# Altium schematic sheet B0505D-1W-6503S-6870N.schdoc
size 277 x 190 mm; Device: default297x210; Symbol: default297x210; Name: default297x210; Size: "A4"; Id: /; File: B0505D-1W-6503S-6870N; Sheet: /
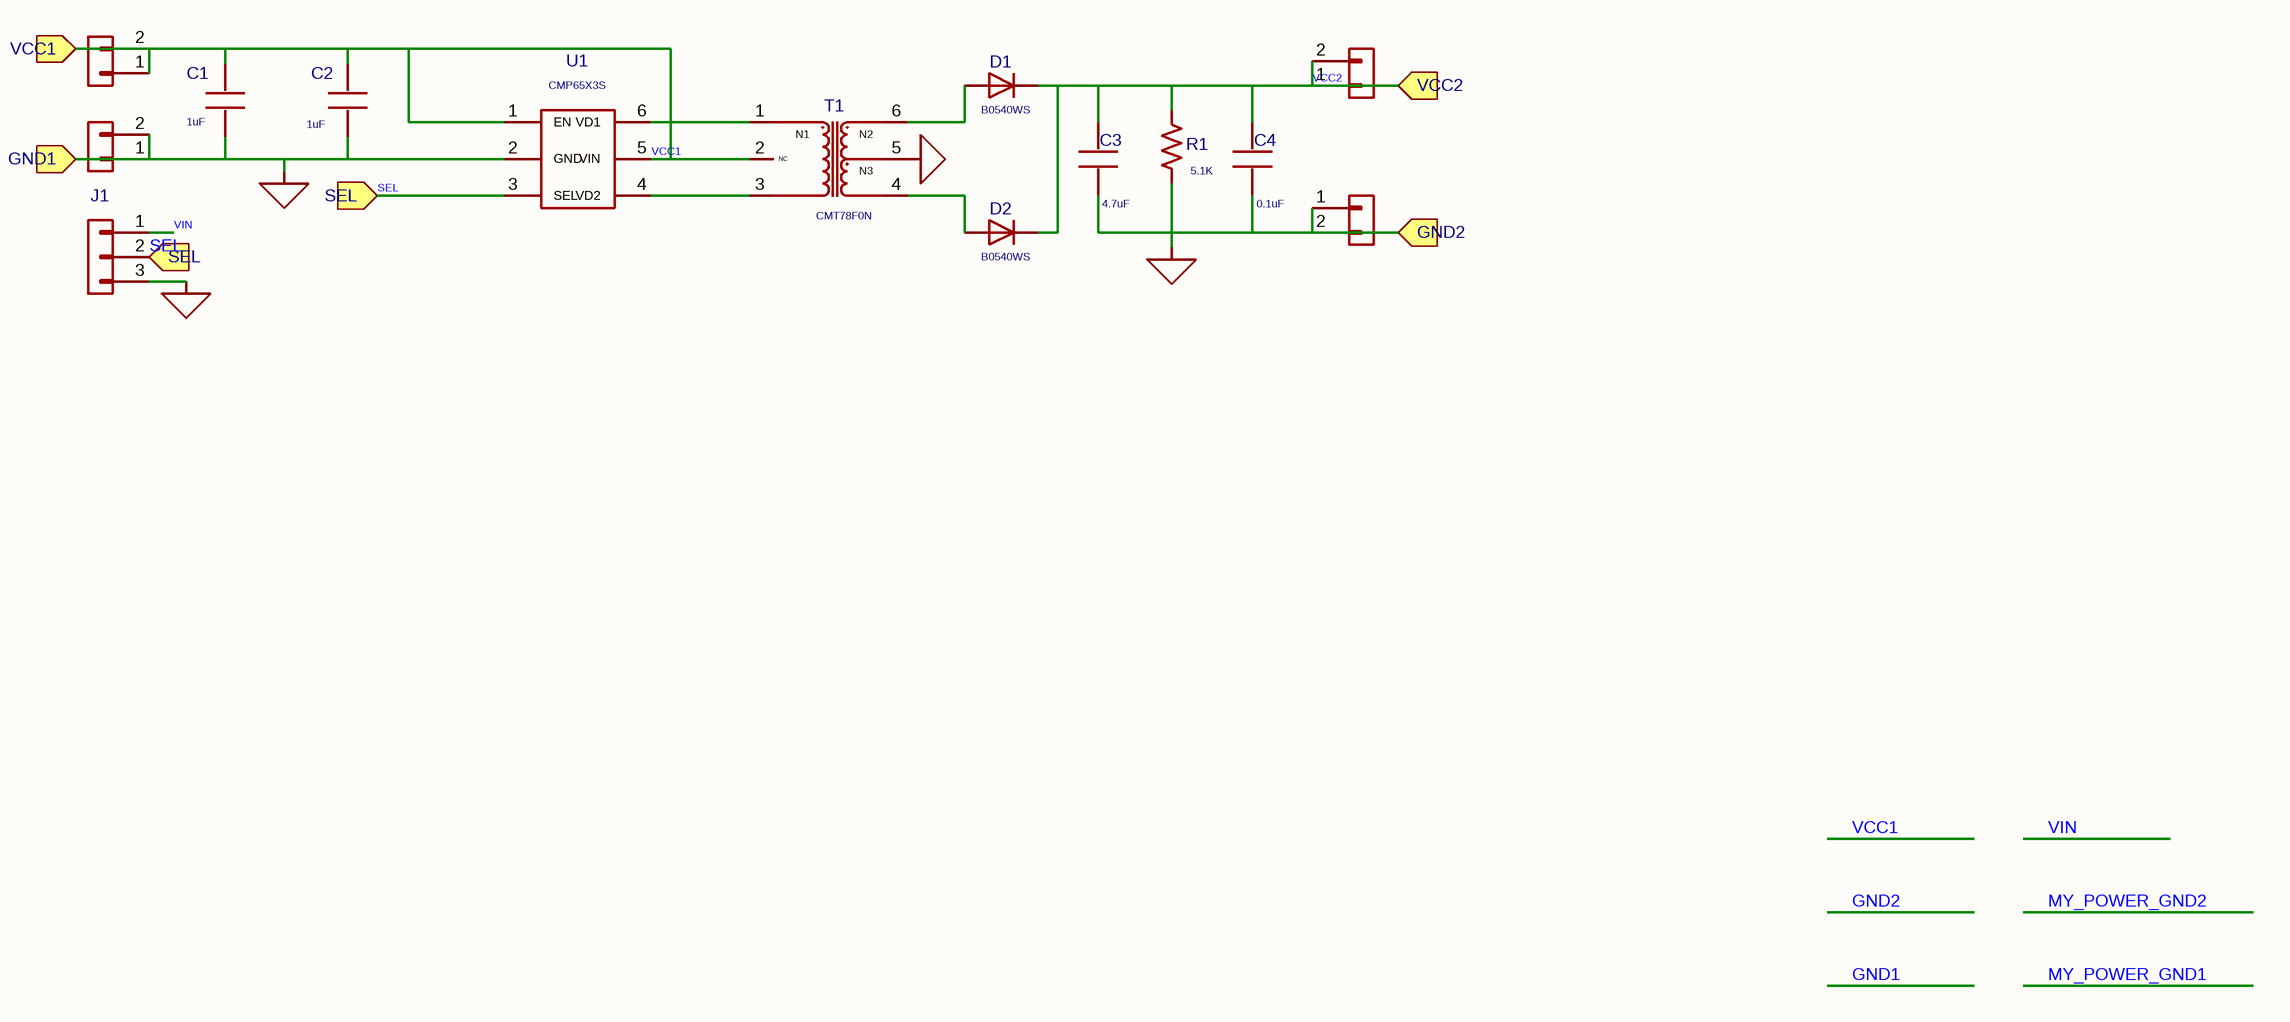
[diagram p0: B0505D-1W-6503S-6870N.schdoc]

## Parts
C1  value 1uF  [MYLibrary:C0603]  (hidden comment: My_Library_C)
C2  value 1uF  [MYLibrary:C0603]  (hidden comment: My_Library_C)
C3  value 4.7uF  [MYLibrary:C0603]  (hidden comment: My_Library_C)
C4  value 0.1uF  [MYLibrary:C0603]  (hidden comment: My_Library_C)
D1  value B0540WS  [Diode_SMD:D_SOD-123F]  (hidden comment: My_Library_D)
D2  value B0540WS  [Diode_SMD:D_SOD-123F]  (hidden comment: My_Library_D)
J1  Connector_Generic_Conn_01x03  [Connector_PinHeader_2.54mm:PinHeader_1x03_P2.54mm_Vertical]  (value not drawn)
J2  Connector_Generic_Conn_01x02  [Connector_PinHeader_2.54mm:PinHeader_1x02_P2.54mm_Vertical]  (value not drawn)
J3  Connector_Generic_Conn_01x02  [Connector_PinHeader_2.54mm:PinHeader_1x02_P2.54mm_Vertical]  (value not drawn)
J4  Connector_Generic_Conn_01x02  [Connector_PinHeader_2.54mm:PinHeader_1x02_P2.54mm_Vertical]  (value not drawn)
J5  Connector_Generic_Conn_01x02  [Connector_PinHeader_2.54mm:PinHeader_1x02_P2.54mm_Vertical]  (value not drawn)
R1  value 5.1K  [MYLibrary:R0603]  (hidden comment: My_Library_R)
T1  value CMT78F0N  [MYLibrary:SMD-6W]  (hidden comment: My_Library_VPT85BB-02A)
U1  value CMP65X3S  [MYLibrary:SOT23-6]  (hidden comment: MyLibrary_CMP6503)

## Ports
GND1 (in), GND2 (in), SEL (in), VCC1 (in), VCC2 (in)

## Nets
MY_POWER_GND1: C1.1 C2.1 J1.3(Pin_3) J3.1(Pin_1) J3.2(Pin_2) U1.2(GND) ; port GND1
MY_POWER_GND2: C3.1 C4.1 J5.1(Pin_1) J5.2(Pin_2) R1.2 T1.5 ; port GND2
SEL: J1.2(Pin_2) U1.3(SEL) ; port SEL
VCC1: C1.2 C2.2 J2.1(Pin_1) J2.2(Pin_2) T1.2 U1.1(EN) U1.5(VIN) ; port VCC1
VCC2: C3.2 C4.2 D1.1(K) D2.1(K) J4.1(Pin_1) J4.2(Pin_2) R1.1 ; port VCC2
VIN: J1.1(Pin_1)
NetD1_2: D1.2(A) T1.6
NetD2_2: D2.2(A) T1.4
NetT1_1: T1.1 U1.6(VD1)
NetT1_3: T1.3 U1.4(VD2)

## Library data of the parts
C1 = My_Library_C: UniqueId: b4693cfd16d534cd; Attribute1: C2; Sheetfile: CMP6503 EV_CMP65X3-02.kicad_sch; ki_description: Unpolarized capacitor; ki_keywords: cap capacitor; AddInBom: yes
C2 = My_Library_C: UniqueId: a2c5d49bc5dde298; Attribute1: C2; Sheetfile: CMP6503 EV_CMP65X3-02.kicad_sch; ki_description: Unpolarized capacitor; ki_keywords: cap capacitor; AddInBom: yes
C3 = My_Library_C: UniqueId: cc82bf2c2e22e605; Attribute1: C2; Sheetfile: CMP6503 EV_CMP65X3-02.kicad_sch; ki_description: Unpolarized capacitor; ki_keywords: cap capacitor; AddInBom: yes
C4 = My_Library_C: UniqueId: 3a68d3ddabf48558; Attribute1: C2; Sheetfile: CMP6503 EV_CMP65X3-02.kicad_sch; ki_description: Unpolarized capacitor; ki_keywords: cap capacitor; AddInBom: yes
D1 = My_Library_D: UniqueId: 6eb2f7ba7a12821c; Attribute1: D1; Sheetfile: CMP6503 EV_CMP65X3-02.kicad_sch; ki_description: Diode; AddInBom: yes
D2 = My_Library_D: UniqueId: cca08e5caf06c018; Attribute1: D1; Sheetfile: CMP6503 EV_CMP65X3-02.kicad_sch; ki_description: Diode; AddInBom: yes
J1 = Connector_Generic_Conn_01x03: UniqueId: 51bfc0e5166a1c40; Attribute1: J1; Sheetfile: CMP6503 EV_CMP65X3-02.kicad_sch; ki_description: Generic connector, single row, 01x03, script generated (kicad-library-utils/schlib/autogen/connector/); AddInBom: yes
J2 = Connector_Generic_Conn_01x02: UniqueId: 1fb9863844ab5169; Attribute1: J5; Sheetfile: CMP6503 EV_CMP65X3-02.kicad_sch; ki_description: Generic connector, single row, 01x02, script generated (kicad-library-utils/schlib/autogen/connector/); AddInBom: yes
J3 = Connector_Generic_Conn_01x02: UniqueId: bd3ee0abdb58119f; Attribute1: J5; Sheetfile: CMP6503 EV_CMP65X3-02.kicad_sch; ki_description: Generic connector, single row, 01x02, script generated (kicad-library-utils/schlib/autogen/connector/); AddInBom: yes
J4 = Connector_Generic_Conn_01x02: UniqueId: 7aadee231938cadd; Attribute1: J5; Sheetfile: CMP6503 EV_CMP65X3-02.kicad_sch; ki_description: Generic connector, single row, 01x02, script generated (kicad-library-utils/schlib/autogen/connector/); AddInBom: yes
J5 = Connector_Generic_Conn_01x02: UniqueId: 188f82074eb8ca32; Attribute1: J5; Sheetfile: CMP6503 EV_CMP65X3-02.kicad_sch; ki_description: Generic connector, single row, 01x02, script generated (kicad-library-utils/schlib/autogen/connector/); AddInBom: yes
R1 = My_Library_R: UniqueId: 353b166cc2dee846; Attribute1: R1; Sheetfile: CMP6503 EV_CMP65X3-02.kicad_sch; ki_description: Resistor; ki_keywords: R res resistor; AddInBom: yes
T1 = My_Library_VPT85BB-02A: UniqueId: 30cfce118f4fe85d; Attribute1: T1; Sheetfile: CMP6503 EV_CMP65X3-02.kicad_sch; AddInBom: yes
U1 = MyLibrary_CMP6503: UniqueId: 1bdc0ab44f99f92d; Attribute1: U1; Sheetfile: CMP6503 EV_CMP65X3-02.kicad_sch; AddInBom: yes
